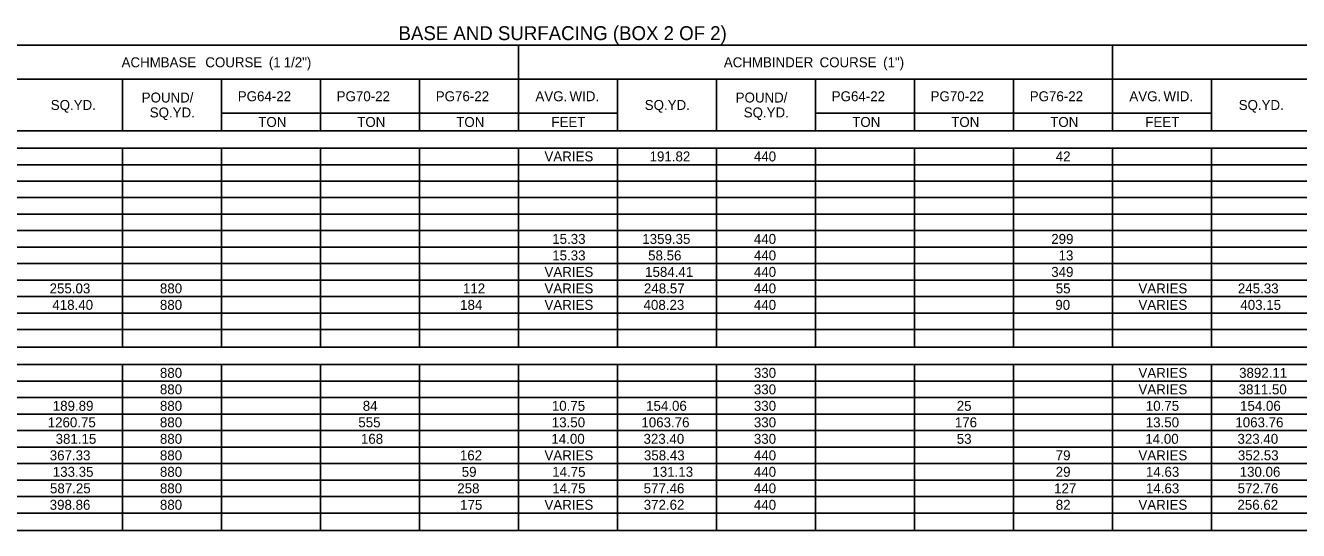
# Model space of a CAD drawing. Extents: x 1226567 to 1228151, y 151309 to 152305.
# Drawn here: x 1227158 to 1227669, y 152060 to 152263 of the extents above; entities that cross this region are included whole.
import ezdxf

# ---------------------------------------------------------------- set-up
doc = ezdxf.new("R2010")
doc.units = 0
doc.layers.add('R_Dimension', color=7, linetype='Continuous')

msp = doc.modelspace()

# ---------------------------------------------------------------- linework, layer by layer
at = {"layer": 'R_Dimension'}
for p, q in [((1226566.84, 152254.68), (1228150.79, 152254.68)), ((1227356.28, 152220.4), (1227356.28, 152254.68)), ((1227594.63, 152220.4), (1227594.63, 152254.68)), ((1226879.58, 152241.04), (1228150.79, 152241.04)), ((1227197.38, 152220.4), (1227197.38, 152241.04)), ((1227237.11, 152220.4), (1227237.11, 152241.04)), ((1227276.83, 152220.4), (1227276.83, 152241.04)), ((1227316.56, 152220.4), (1227316.56, 152241.04)), ((1227396.01, 152220.4), (1227396.01, 152241.04)), ((1227435.73, 152220.4), (1227435.73, 152241.04)), ((1227475.46, 152220.4), (1227475.46, 152241.04)), ((1227515.18, 152220.4), (1227515.18, 152241.04)), ((1227554.91, 152220.4), (1227554.91, 152241.04)), ((1227634.36, 152220.4), (1227634.36, 152241.04)), ((1227237.11, 152227.41), (1227396.01, 152227.41)), ((1227475.46, 152227.41), (1227634.36, 152227.41)), ((1226566.84, 152220.4), (1228150.79, 152220.4)), ((1226566.84, 152220.4), (1228150.79, 152220.4)), ((1227157.66, 152220.4), (1227396.01, 152220.4)), ((1227396.01, 152220.4), (1227634.36, 152220.4)), ((1227634.36, 152220.4), (1227872.71, 152220.4)), ((1226566.84, 152213.39), (1228150.79, 152213.39)), ((1227197.38, 152133.55), (1227197.38, 152213.39)), ((1227237.11, 152133.55), (1227237.11, 152213.39)), ((1227276.83, 152133.55), (1227276.83, 152213.39)), ((1227316.56, 152133.55), (1227316.56, 152213.39)), ((1227356.28, 152133.55), (1227356.28, 152213.39)), ((1227396.01, 152133.55), (1227396.01, 152213.39)), ((1227435.73, 152133.55), (1227435.73, 152213.39)), ((1227475.46, 152133.55), (1227475.46, 152213.39)), ((1227515.18, 152133.55), (1227515.18, 152213.39)), ((1227554.91, 152133.55), (1227554.91, 152213.39)), ((1227594.63, 152133.55), (1227594.63, 152213.39)), ((1227634.36, 152133.55), (1227634.36, 152213.39)), ((1226566.84, 152206.77), (1228150.79, 152206.77)), ((1226566.84, 152200.15), (1228150.79, 152200.15)), ((1226566.84, 152193.53), (1228150.79, 152193.53)), ((1226566.84, 152186.91), (1228150.79, 152186.91)), ((1226566.84, 152180.29), (1228150.79, 152180.29)), ((1226566.84, 152173.67), (1228150.79, 152173.67)), ((1226566.84, 152167.05), (1228150.79, 152167.05)), ((1226566.84, 152160.43), (1228150.79, 152160.43)), ((1226566.84, 152153.8), (1228150.79, 152153.8)), ((1226566.84, 152147.18), (1228150.79, 152147.18)), ((1226566.84, 152140.56), (1228150.79, 152140.56)), ((1226566.84, 152133.55), (1228150.79, 152133.55)), ((1226566.84, 152126.54), (1228150.79, 152126.54)), ((1227197.38, 152059.94), (1227197.38, 152126.54)), ((1227237.11, 152059.94), (1227237.11, 152126.54)), ((1227276.83, 152059.94), (1227276.83, 152126.54)), ((1227316.56, 152059.94), (1227316.56, 152126.54)), ((1227356.28, 152059.94), (1227356.28, 152126.54)), ((1227396.01, 152059.94), (1227396.01, 152126.54)), ((1227435.73, 152059.94), (1227435.73, 152126.54)), ((1227475.46, 152059.94), (1227475.46, 152126.54)), ((1227515.18, 152059.94), (1227515.18, 152126.54)), ((1227554.91, 152059.94), (1227554.91, 152126.54)), ((1227594.63, 152059.94), (1227594.63, 152126.54)), ((1227634.36, 152059.94), (1227634.36, 152126.54)), ((1226566.84, 152119.92), (1228150.79, 152119.92)), ((1226566.84, 152113.3), (1228150.79, 152113.3)), ((1226566.84, 152106.68), (1228150.79, 152106.68)), ((1226566.84, 152100.06), (1228150.79, 152100.06)), ((1226566.84, 152093.44), (1228150.79, 152093.44)), ((1226566.84, 152086.82), (1228150.79, 152086.82)), ((1226566.84, 152080.2), (1228150.79, 152080.2)), ((1226566.84, 152073.58), (1228150.79, 152073.58)), ((1226566.84, 152066.95), (1228150.79, 152066.95)), ((1226566.84, 152059.94), (1228150.79, 152059.94))]:
    msp.add_line(p, q, dxfattribs=at)

# ---------------------------------------------------------------- texts
for s, height, p in [('BASE AND SURFACING (BOX 2 OF 2)', 5.5923, (1227308.11, 152256.75)), ('ACHM', 3.994, (1227196.98, 152245.86)), (' BASE', 3.994, (1227211.19, 152245.86)), (' COURSE', 3.994, (1227229.09, 152245.86)), (' (1', 3.994, (1227254.6, 152245.86)), (' 1/2")', 3.994, (1227260.54, 152245.86)), ('ACHM', 3.994, (1227438.66, 152245.86)), (' BINDER', 3.994, (1227452.88, 152245.86)), (' COURSE', 3.994, (1227475.59, 152245.86)), (' (1")', 3.994, (1227501.09, 152245.86)), ('POUND', 3.994, (1227205.06, 152231.72)), (' /', 3.994, (1227222.83, 152231.72)), ('PG', 3.994, (1227243.6, 152232.23)), (' 64-22', 3.994, (1227249.86, 152232.23)), ('PG', 3.994, (1227283.27, 152232.23)), (' 70-22', 3.994, (1227289.53, 152232.23)), ('PG', 3.994, (1227323.05, 152232.23)), (' 76-22', 3.994, (1227329.31, 152232.23)), ('AVG.', 3.994, (1227363.05, 152232.23)), (' WID.', 3.994, (1227375.25, 152232.23)), ('POUND', 3.994, (1227443.41, 152231.72)), (' /', 3.994, (1227461.18, 152231.72)), ('PG', 3.994, (1227481.95, 152232.23)), (' 64-22', 3.994, (1227488.21, 152232.23)), ('PG', 3.994, (1227521.62, 152232.23)), (' 70-22', 3.994, (1227527.88, 152232.23)), ('PG', 3.994, (1227561.41, 152232.23)), (' 76-22', 3.994, (1227567.66, 152232.23)), ('AVG.', 3.994, (1227601.4, 152232.23)), (' WID.', 3.994, (1227613.6, 152232.23)), ('SQ.YD.', 3.994, (1227168.56, 152228.73)), ('SQ.YD.', 3.994, (1227208.28, 152225.73)), ('SQ.YD.', 3.994, (1227406.91, 152228.73)), ('SQ.YD.', 3.994, (1227446.63, 152225.73)), ('SQ.YD.', 3.994, (1227645.26, 152228.73)), ('TON', 3.994, (1227251.83, 152221.91)), ('TON', 3.994, (1227291.55, 152221.91)), ('TON', 3.994, (1227331.28, 152221.91)), ('FEET', 3.994, (1227369.46, 152221.91)), ('TON', 3.994, (1227490.18, 152221.91)), ('TON', 3.994, (1227529.9, 152221.91)), ('TON', 3.994, (1227569.63, 152221.91)), ('FEET', 3.994, (1227607.81, 152221.91)), ('VARIES', 3.994, (1227366.68, 152208.08)), ('191.82', 3.994, (1227408.86, 152208.08)), ('440', 3.994, (1227450.71, 152208.08)), ('42', 3.994, (1227571.85, 152208.08)), ('15.33', 3.994, (1227369.79, 152174.98)), ('1359.35', 3.994, (1227405.93, 152174.98)), ('440', 3.994, (1227450.71, 152174.98)), ('299', 3.994, (1227570.04, 152174.98)), ('15.33', 3.994, (1227369.79, 152168.36)), ('58.56', 3.994, (1227408.28, 152168.36)), ('440', 3.994, (1227450.71, 152168.36)), ('13', 3.994, (1227572.98, 152168.36)), ('VARIES', 3.994, (1227366.68, 152161.74)), ('1584.41', 3.994, (1227407.07, 152161.74)), ('440', 3.994, (1227450.71, 152161.74)), ('349', 3.994, (1227570.04, 152161.74)), ('255.03', 3.994, (1227168.09, 152155.12)), ('880', 3.994, (1227212.36, 152155.12)), ('112', 3.994, (1227333.97, 152155.12)), ('VARIES', 3.994, (1227366.68, 152155.12)), ('248.57', 3.994, (1227406.59, 152155.12)), ('440', 3.994, (1227450.71, 152155.12)), ('55', 3.994, (1227571.85, 152155.12)), ('VARIES', 3.994, (1227605.03, 152155.12)), ('245.33', 3.994, (1227644.94, 152155.12)), ('418.40', 3.994, (1227169.2, 152148.5)), ('880', 3.994, (1227212.36, 152148.5)), ('184', 3.994, (1227332.84, 152148.5)), ('VARIES', 3.994, (1227366.68, 152148.5)), ('408.23', 3.994, (1227406.44, 152148.5)), ('440', 3.994, (1227450.71, 152148.5)), ('90', 3.994, (1227571.67, 152148.5)), ('VARIES', 3.994, (1227605.03, 152148.5)), ('403.15', 3.994, (1227645.92, 152148.5)), ('880', 3.994, (1227212.36, 152121.23)), ('330', 3.994, (1227450.71, 152121.23)), ('VARIES', 3.994, (1227605.03, 152121.23)), ('3892.11', 3.994, (1227645.42, 152121.23)), ('880', 3.994, (1227212.36, 152114.61)), ('330', 3.994, (1227450.71, 152114.61)), ('VARIES', 3.994, (1227605.03, 152114.61)), ('3811.50', 3.994, (1227645.24, 152114.61)), ('189.89', 3.994, (1227169.36, 152107.99)), ('880', 3.994, (1227212.36, 152107.99)), ('84', 3.994, (1227293.77, 152107.99)), ('10.75', 3.994, (1227369.64, 152107.99)), ('154.06', 3.994, (1227407.46, 152107.99)), ('330', 3.994, (1227450.71, 152107.99)), ('25', 3.994, (1227532.12, 152107.99)), ('10.75', 3.994, (1227607.99, 152107.99)), ('154.06', 3.994, (1227645.81, 152107.99)), ('1260.75', 3.994, (1227167.33, 152101.37)), ('880', 3.994, (1227212.36, 152101.37)), ('555', 3.994, (1227291.98, 152101.37)), ('13.50', 3.994, (1227369.62, 152101.37)), ('1063.76', 3.994, (1227405.57, 152101.37)), ('330', 3.994, (1227450.71, 152101.37)), ('176', 3.994, (1227531.35, 152101.37)), ('13.50', 3.994, (1227607.97, 152101.37)), ('1063.76', 3.994, (1227643.92, 152101.37)), ('381.15', 3.994, (1227170.51, 152094.75)), ('880', 3.994, (1227212.36, 152094.75)), ('168', 3.994, (1227293.02, 152094.75)), ('14.00', 3.994, (1227369.46, 152094.75)), ('323.40', 3.994, (1227406.42, 152094.75)), ('330', 3.994, (1227450.71, 152094.75)), ('53', 3.994, (1227532.12, 152094.75)), ('14.00', 3.994, (1227607.81, 152094.75)), ('323.40', 3.994, (1227644.77, 152094.75)), ('367.33', 3.994, (1227168.15, 152088.13)), ('880', 3.994, (1227212.36, 152088.13)), ('162', 3.994, (1227332.74, 152088.13)), ('VARIES', 3.994, (1227366.68, 152088.13)), ('358.43', 3.994, (1227406.59, 152088.13)), ('440', 3.994, (1227450.71, 152088.13)), ('79', 3.994, (1227571.83, 152088.13)), ('VARIES', 3.994, (1227605.03, 152088.13)), ('352.53', 3.994, (1227644.94, 152088.13)), ('133.35', 3.994, (1227169.37, 152081.51)), ('880', 3.994, (1227212.36, 152081.51)), ('59', 3.994, (1227333.48, 152081.51)), ('14.75', 3.994, (1227369.79, 152081.51)), ('131.13', 3.994, (1227409.99, 152081.51)), ('440', 3.994, (1227450.71, 152081.51)), ('29', 3.994, (1227571.83, 152081.51)), ('14.63', 3.994, (1227608.05, 152081.51)), ('130.06', 3.994, (1227645.65, 152081.51)), ('587.25', 3.994, (1227168.24, 152074.89)), ('880', 3.994, (1227212.36, 152074.89)), ('258', 3.994, (1227331.7, 152074.89)), ('14.75', 3.994, (1227369.79, 152074.89)), ('577.46', 3.994, (1227406.48, 152074.89)), ('440', 3.994, (1227450.71, 152074.89)), ('127', 3.994, (1227571.19, 152074.89)), ('14.63', 3.994, (1227608.05, 152074.89)), ('572.76', 3.994, (1227644.83, 152074.89)), ('398.86', 3.994, (1227168.13, 152068.27)), ('880', 3.994, (1227212.36, 152068.27)), ('175', 3.994, (1227332.84, 152068.27)), ('VARIES', 3.994, (1227366.68, 152068.27)), ('372.62', 3.994, (1227406.5, 152068.27)), ('440', 3.994, (1227450.71, 152068.27)), ('82', 3.994, (1227571.85, 152068.27)), ('VARIES', 3.994, (1227605.03, 152068.27)), ('256.62', 3.994, (1227644.76, 152068.27))]:
    msp.add_text(s, height=height, dxfattribs=at).set_placement(p)

doc.saveas('drawing.dxf')
